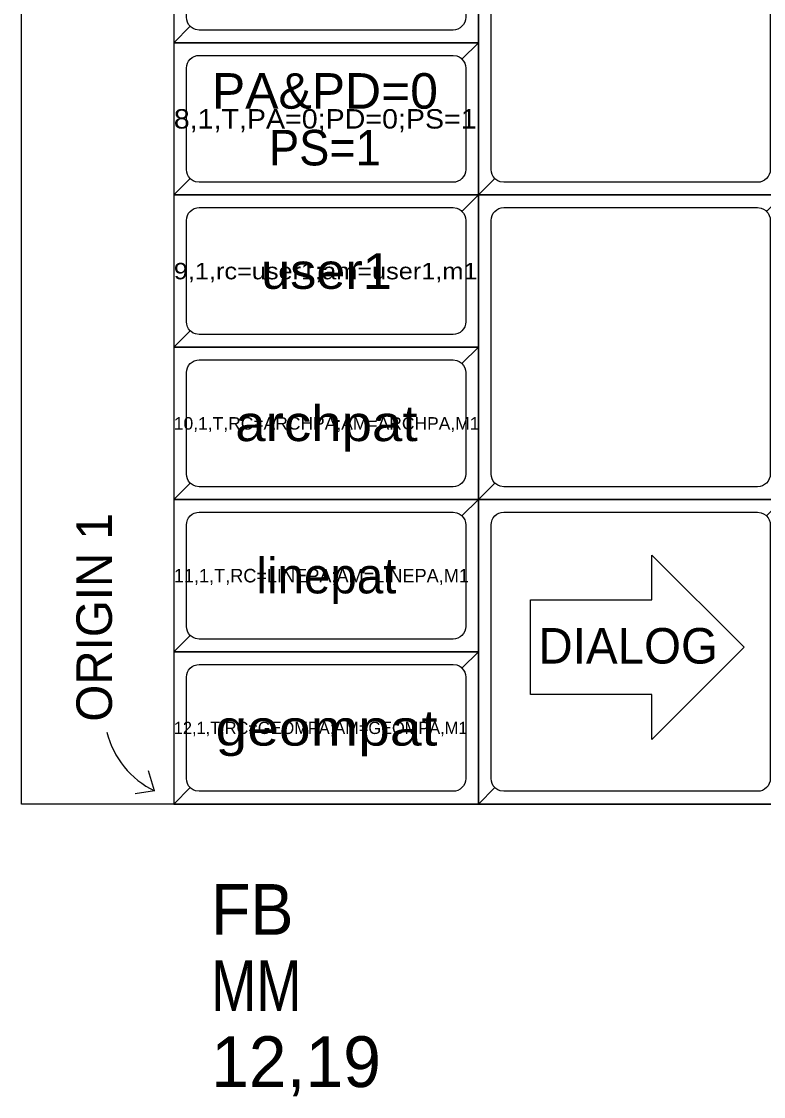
# Model space of a CAD drawing. Extents: x 67896 to 67908, y 49158.5 to 49162.6.
# Drawn here: x 67895.989 to 67897.451, y 49158.457 to 49160.575 of the extents above; entities that cross this region are included whole.
import ezdxf
from ezdxf.enums import TextEntityAlignment as Align

# ---------------------------------------------------------------- set-up
doc = ezdxf.new("R2010")
doc.units = 0
doc.header["$LTSCALE"] = 0.02
for name, color, linetype, lineweight in [('1', 7, 'Continuous', 25), ('2', 7, 'Continuous', 25), ('3', 7, 'Continuous', 25), ('4', 7, 'Continuous', 25), ('5', 7, 'Continuous', 25)]:
    doc.layers.add(name, color=color, linetype=linetype, lineweight=lineweight)
for name, color, linetype in [('63', 7, 'Continuous'), ('7', 7, 'Continuous'), ('8', 7, 'Continuous'), ('9', 7, 'Continuous')]:
    doc.layers.add(name, color=color, linetype=linetype)

msp = doc.modelspace()

# ---------------------------------------------------------------- linework, layer by layer
at = {"layer": '1'}
for points in [[(67896.2889, 49160.5331), (67896.8889, 49160.5331), (67896.8889, 49160.8331), (67896.2889, 49160.8331)], [(67896.8889, 49160.2331), (67897.4889, 49160.2331), (67897.4889, 49160.8331), (67896.8889, 49160.8331)], [(67896.2889, 49160.2331), (67896.8889, 49160.2331), (67896.8889, 49160.5331), (67896.2889, 49160.5331)], [(67896.2889, 49159.9331), (67896.8889, 49159.9331), (67896.8889, 49160.2331), (67896.2889, 49160.2331)], [(67896.8889, 49159.6331), (67897.4889, 49159.6331), (67897.4889, 49160.2331), (67896.8889, 49160.2331)], [(67896.2889, 49159.6331), (67896.8889, 49159.6331), (67896.8889, 49159.9331), (67896.2889, 49159.9331)], [(67896.2889, 49159.3331), (67896.8889, 49159.3331), (67896.8889, 49159.6331), (67896.2889, 49159.6331)], [(67896.8889, 49159.0331), (67897.4889, 49159.0331), (67897.4889, 49159.6331), (67896.8889, 49159.6331)], [(67896.2889, 49159.0331), (67896.8889, 49159.0331), (67896.8889, 49159.3331), (67896.2889, 49159.3331)]]:
    msp.add_lwpolyline(points, close=True, dxfattribs=at)
at = {"layer": '2'}
for points in [[(67907.9889, 49159.0331), (67895.9889, 49159.0331), (67895.9889, 49162.6331), (67907.9889, 49162.6331)], [(67896.2889, 49160.5331), (67896.8889, 49160.5331), (67896.8889, 49160.8331), (67896.2889, 49160.8331)], [(67896.8889, 49160.2331), (67897.4889, 49160.2331), (67897.4889, 49160.8331), (67896.8889, 49160.8331)], [(67896.2889, 49160.2331), (67896.8889, 49160.2331), (67896.8889, 49160.5331), (67896.2889, 49160.5331)], [(67896.2889, 49159.9331), (67896.8889, 49159.9331), (67896.8889, 49160.2331), (67896.2889, 49160.2331)], [(67896.8889, 49159.6331), (67897.4889, 49159.6331), (67897.4889, 49160.2331), (67896.8889, 49160.2331)], [(67896.2889, 49159.6331), (67896.8889, 49159.6331), (67896.8889, 49159.9331), (67896.2889, 49159.9331)], [(67896.2889, 49159.3331), (67896.8889, 49159.3331), (67896.8889, 49159.6331), (67896.2889, 49159.6331)], [(67896.8889, 49159.0331), (67897.4889, 49159.0331), (67897.4889, 49159.6331), (67896.8889, 49159.6331)], [(67896.2889, 49159.0331), (67896.8889, 49159.0331), (67896.8889, 49159.3331), (67896.2889, 49159.3331)]]:
    msp.add_lwpolyline(points, close=True, dxfattribs=at)
at = {"layer": '3'}
for points in [[(67896.8889, 49160.8331), (67896.2889, 49160.8331), (67896.2889, 49160.5331), (67896.3212, 49160.5654), (67896.3181, 49160.5692), (67896.3158, 49160.5735), (67896.3144, 49160.5782), (67896.3139, 49160.5831), (67896.3139, 49160.7831), (67896.3144, 49160.788), (67896.3158, 49160.7927), (67896.3181, 49160.797), (67896.3212, 49160.8008), (67896.3212, 49160.8008), (67896.325, 49160.8039), (67896.3293, 49160.8062), (67896.334, 49160.8076), (67896.3389, 49160.8081), (67896.8389, 49160.8081), (67896.8462, 49160.807), (67896.8507, 49160.8051), (67896.8548, 49160.8024), (67896.8566, 49160.8008)], [(67897.4889, 49160.8331), (67896.8889, 49160.8331), (67896.8889, 49160.2331), (67896.9212, 49160.2654), (67896.9181, 49160.2692), (67896.9158, 49160.2735), (67896.9144, 49160.2782), (67896.9139, 49160.2831), (67896.9139, 49160.7831), (67896.9144, 49160.788), (67896.9158, 49160.7927), (67896.9181, 49160.797), (67896.9212, 49160.8008), (67896.9212, 49160.8008), (67896.925, 49160.8039), (67896.9293, 49160.8062), (67896.934, 49160.8076), (67896.9389, 49160.8081), (67897.4389, 49160.8081), (67897.4462, 49160.807), (67897.4507, 49160.8051), (67897.4548, 49160.8024), (67897.4566, 49160.8008)], [(67896.8889, 49160.5331), (67896.2889, 49160.5331), (67896.2889, 49160.2331), (67896.3212, 49160.2654), (67896.3181, 49160.2692), (67896.3158, 49160.2735), (67896.3144, 49160.2782), (67896.3139, 49160.2831), (67896.3139, 49160.4831), (67896.3144, 49160.488), (67896.3158, 49160.4927), (67896.3181, 49160.497), (67896.3212, 49160.5008), (67896.3212, 49160.5008), (67896.325, 49160.5039), (67896.3293, 49160.5062), (67896.334, 49160.5076), (67896.3389, 49160.5081), (67896.8389, 49160.5081), (67896.8462, 49160.507), (67896.8507, 49160.5051), (67896.8548, 49160.5024), (67896.8566, 49160.5008)], [(67896.8889, 49160.2331), (67896.2889, 49160.2331), (67896.2889, 49159.9331), (67896.3212, 49159.9654), (67896.3181, 49159.9692), (67896.3158, 49159.9735), (67896.3144, 49159.9782), (67896.3139, 49159.9831), (67896.3139, 49160.1831), (67896.3144, 49160.188), (67896.3158, 49160.1927), (67896.3181, 49160.197), (67896.3212, 49160.2008), (67896.3212, 49160.2008), (67896.325, 49160.2039), (67896.3293, 49160.2062), (67896.334, 49160.2076), (67896.3389, 49160.2081), (67896.8389, 49160.2081), (67896.8462, 49160.207), (67896.8507, 49160.2051), (67896.8548, 49160.2024), (67896.8566, 49160.2008)], [(67897.4889, 49160.2331), (67896.8889, 49160.2331), (67896.8889, 49159.6331), (67896.9212, 49159.6654), (67896.9181, 49159.6692), (67896.9158, 49159.6735), (67896.9144, 49159.6782), (67896.9139, 49159.6831), (67896.9139, 49160.1831), (67896.9144, 49160.188), (67896.9158, 49160.1927), (67896.9181, 49160.197), (67896.9212, 49160.2008), (67896.9212, 49160.2008), (67896.925, 49160.2039), (67896.9293, 49160.2062), (67896.934, 49160.2076), (67896.9389, 49160.2081), (67897.4389, 49160.2081), (67897.4462, 49160.207), (67897.4507, 49160.2051), (67897.4548, 49160.2024), (67897.4566, 49160.2008)], [(67896.8889, 49159.9331), (67896.2889, 49159.9331), (67896.2889, 49159.6331), (67896.3212, 49159.6654), (67896.3181, 49159.6692), (67896.3158, 49159.6735), (67896.3144, 49159.6782), (67896.3139, 49159.6831), (67896.3139, 49159.8831), (67896.3144, 49159.888), (67896.3158, 49159.8927), (67896.3181, 49159.897), (67896.3212, 49159.9008), (67896.3212, 49159.9008), (67896.325, 49159.9039), (67896.3293, 49159.9062), (67896.334, 49159.9076), (67896.3389, 49159.9081), (67896.8389, 49159.9081), (67896.8462, 49159.907), (67896.8507, 49159.9051), (67896.8548, 49159.9024), (67896.8566, 49159.9008)], [(67896.8889, 49159.6331), (67896.2889, 49159.6331), (67896.2889, 49159.3331), (67896.3212, 49159.3654), (67896.3181, 49159.3692), (67896.3158, 49159.3735), (67896.3144, 49159.3782), (67896.3139, 49159.3831), (67896.3139, 49159.5831), (67896.3144, 49159.588), (67896.3158, 49159.5927), (67896.3181, 49159.597), (67896.3212, 49159.6008), (67896.3212, 49159.6008), (67896.325, 49159.6039), (67896.3293, 49159.6062), (67896.334, 49159.6076), (67896.3389, 49159.6081), (67896.8389, 49159.6081), (67896.8462, 49159.607), (67896.8507, 49159.6051), (67896.8548, 49159.6024), (67896.8566, 49159.6008)], [(67897.4889, 49159.6331), (67896.8889, 49159.6331), (67896.8889, 49159.0331), (67896.9212, 49159.0654), (67896.9181, 49159.0692), (67896.9158, 49159.0735), (67896.9144, 49159.0782), (67896.9139, 49159.0831), (67896.9139, 49159.5831), (67896.9144, 49159.588), (67896.9158, 49159.5927), (67896.9181, 49159.597), (67896.9212, 49159.6008), (67896.9212, 49159.6008), (67896.925, 49159.6039), (67896.9293, 49159.6062), (67896.934, 49159.6076), (67896.9389, 49159.6081), (67897.4389, 49159.6081), (67897.4462, 49159.607), (67897.4507, 49159.6051), (67897.4548, 49159.6024), (67897.4566, 49159.6008)], [(67896.8889, 49159.3331), (67896.2889, 49159.3331), (67896.2889, 49159.0331), (67896.3212, 49159.0654), (67896.3181, 49159.0692), (67896.3158, 49159.0735), (67896.3144, 49159.0782), (67896.3139, 49159.0831), (67896.3139, 49159.2831), (67896.3144, 49159.288), (67896.3158, 49159.2927), (67896.3181, 49159.297), (67896.3212, 49159.3008), (67896.3212, 49159.3008), (67896.325, 49159.3039), (67896.3293, 49159.3062), (67896.334, 49159.3076), (67896.3389, 49159.3081), (67896.8389, 49159.3081), (67896.8462, 49159.307), (67896.8507, 49159.3051), (67896.8548, 49159.3024), (67896.8566, 49159.3008)]]:
    msp.add_lwpolyline(points, close=True, dxfattribs=at)
at = {"layer": '4'}
for points in [[(67896.2889, 49160.5331), (67896.8889, 49160.5331), (67896.8889, 49160.8331), (67896.8566, 49160.8008), (67896.8597, 49160.797), (67896.862, 49160.7927), (67896.8634, 49160.788), (67896.8639, 49160.7831), (67896.8639, 49160.5831), (67896.8634, 49160.5782), (67896.862, 49160.5735), (67896.8597, 49160.5692), (67896.8566, 49160.5654), (67896.8566, 49160.5654), (67896.8528, 49160.5623), (67896.8485, 49160.56), (67896.8438, 49160.5586), (67896.8389, 49160.5581), (67896.3389, 49160.5581), (67896.3316, 49160.5592), (67896.3271, 49160.5611), (67896.323, 49160.5638), (67896.3212, 49160.5654)], [(67896.8889, 49160.2331), (67897.4889, 49160.2331), (67897.4889, 49160.8331), (67897.4566, 49160.8008), (67897.4597, 49160.797), (67897.462, 49160.7927), (67897.4634, 49160.788), (67897.4639, 49160.7831), (67897.4639, 49160.2831), (67897.4634, 49160.2782), (67897.462, 49160.2735), (67897.4597, 49160.2692), (67897.4566, 49160.2654), (67897.4566, 49160.2654), (67897.4528, 49160.2623), (67897.4485, 49160.26), (67897.4438, 49160.2586), (67897.4389, 49160.2581), (67896.9389, 49160.2581), (67896.9316, 49160.2592), (67896.9271, 49160.2611), (67896.923, 49160.2638), (67896.9212, 49160.2654)], [(67896.2889, 49160.2331), (67896.8889, 49160.2331), (67896.8889, 49160.5331), (67896.8566, 49160.5008), (67896.8597, 49160.497), (67896.862, 49160.4927), (67896.8634, 49160.488), (67896.8639, 49160.4831), (67896.8639, 49160.2831), (67896.8634, 49160.2782), (67896.862, 49160.2735), (67896.8597, 49160.2692), (67896.8566, 49160.2654), (67896.8566, 49160.2654), (67896.8528, 49160.2623), (67896.8485, 49160.26), (67896.8438, 49160.2586), (67896.8389, 49160.2581), (67896.3389, 49160.2581), (67896.3316, 49160.2592), (67896.3271, 49160.2611), (67896.323, 49160.2638), (67896.3212, 49160.2654)], [(67896.2889, 49159.9331), (67896.8889, 49159.9331), (67896.8889, 49160.2331), (67896.8566, 49160.2008), (67896.8597, 49160.197), (67896.862, 49160.1927), (67896.8634, 49160.188), (67896.8639, 49160.1831), (67896.8639, 49159.9831), (67896.8634, 49159.9782), (67896.862, 49159.9735), (67896.8597, 49159.9692), (67896.8566, 49159.9654), (67896.8566, 49159.9654), (67896.8528, 49159.9623), (67896.8485, 49159.96), (67896.8438, 49159.9586), (67896.8389, 49159.9581), (67896.3389, 49159.9581), (67896.3316, 49159.9592), (67896.3271, 49159.9611), (67896.323, 49159.9638), (67896.3212, 49159.9654)], [(67896.8889, 49159.6331), (67897.4889, 49159.6331), (67897.4889, 49160.2331), (67897.4566, 49160.2008), (67897.4597, 49160.197), (67897.462, 49160.1927), (67897.4634, 49160.188), (67897.4639, 49160.1831), (67897.4639, 49159.6831), (67897.4634, 49159.6782), (67897.462, 49159.6735), (67897.4597, 49159.6692), (67897.4566, 49159.6654), (67897.4566, 49159.6654), (67897.4528, 49159.6623), (67897.4485, 49159.66), (67897.4438, 49159.6586), (67897.4389, 49159.6581), (67896.9389, 49159.6581), (67896.9316, 49159.6592), (67896.9271, 49159.6611), (67896.923, 49159.6638), (67896.9212, 49159.6654)], [(67896.2889, 49159.6331), (67896.8889, 49159.6331), (67896.8889, 49159.9331), (67896.8566, 49159.9008), (67896.8597, 49159.897), (67896.862, 49159.8927), (67896.8634, 49159.888), (67896.8639, 49159.8831), (67896.8639, 49159.6831), (67896.8634, 49159.6782), (67896.862, 49159.6735), (67896.8597, 49159.6692), (67896.8566, 49159.6654), (67896.8566, 49159.6654), (67896.8528, 49159.6623), (67896.8485, 49159.66), (67896.8438, 49159.6586), (67896.8389, 49159.6581), (67896.3389, 49159.6581), (67896.3316, 49159.6592), (67896.3271, 49159.6611), (67896.323, 49159.6638), (67896.3212, 49159.6654)], [(67896.2889, 49159.3331), (67896.8889, 49159.3331), (67896.8889, 49159.6331), (67896.8566, 49159.6008), (67896.8597, 49159.597), (67896.862, 49159.5927), (67896.8634, 49159.588), (67896.8639, 49159.5831), (67896.8639, 49159.3831), (67896.8634, 49159.3782), (67896.862, 49159.3735), (67896.8597, 49159.3692), (67896.8566, 49159.3654), (67896.8566, 49159.3654), (67896.8528, 49159.3623), (67896.8485, 49159.36), (67896.8438, 49159.3586), (67896.8389, 49159.3581), (67896.3389, 49159.3581), (67896.3316, 49159.3592), (67896.3271, 49159.3611), (67896.323, 49159.3638), (67896.3212, 49159.3654)], [(67896.8889, 49159.0331), (67897.4889, 49159.0331), (67897.4889, 49159.6331), (67897.4566, 49159.6008), (67897.4597, 49159.597), (67897.462, 49159.5927), (67897.4634, 49159.588), (67897.4639, 49159.5831), (67897.4639, 49159.0831), (67897.4634, 49159.0782), (67897.462, 49159.0735), (67897.4597, 49159.0692), (67897.4566, 49159.0654), (67897.4566, 49159.0654), (67897.4528, 49159.0623), (67897.4485, 49159.06), (67897.4438, 49159.0586), (67897.4389, 49159.0581), (67896.9389, 49159.0581), (67896.9316, 49159.0592), (67896.9271, 49159.0611), (67896.923, 49159.0638), (67896.9212, 49159.0654)], [(67896.2889, 49159.0331), (67896.8889, 49159.0331), (67896.8889, 49159.3331), (67896.8566, 49159.3008), (67896.8597, 49159.297), (67896.862, 49159.2927), (67896.8634, 49159.288), (67896.8639, 49159.2831), (67896.8639, 49159.0831), (67896.8634, 49159.0782), (67896.862, 49159.0735), (67896.8597, 49159.0692), (67896.8566, 49159.0654), (67896.8566, 49159.0654), (67896.8528, 49159.0623), (67896.8485, 49159.06), (67896.8438, 49159.0586), (67896.8389, 49159.0581), (67896.3389, 49159.0581), (67896.3316, 49159.0592), (67896.3271, 49159.0611), (67896.323, 49159.0638), (67896.3212, 49159.0654)]]:
    msp.add_lwpolyline(points, close=True, dxfattribs=at)
at = {"layer": '5'}
for q in [(67896.239, 49159.0982), (67896.2129, 49159.0532)]:
    msp.add_line((67896.2509, 49159.0591), q, dxfattribs=at)
msp.add_lwpolyline([(67897.2305, 49159.5236), (67897.4121, 49159.3421), (67897.2305, 49159.1605), (67897.2305, 49159.2486), (67896.9918, 49159.2486), (67896.9918, 49159.4356), (67897.2305, 49159.4356)], close=True, dxfattribs=at)
msp.add_arc((67896.3275, 49159.217), 0.1755, 193.9079, 244.0981, dxfattribs=at)

# ---------------------------------------------------------------- texts
for s, width, p in [('PA&PD=0', 1.05, (67896.5866, 49160.4031)), ('PS=1', 0.95, (67896.5866, 49160.2913))]:
    msp.add_text(s, height=0.07, dxfattribs=dict(at, width=width)).set_placement(p, align=Align.CENTER)
msp.add_text('ORIGIN 1', height=0.07, rotation=90, dxfattribs=at).set_placement((67896.1671, 49159.4008), align=Align.CENTER)
msp.add_text('DIALOG', height=0.07, dxfattribs=at).set_placement((67897.184, 49159.3098), align=Align.CENTER)
at = {"layer": '63'}
for s, height, width, p in [('8,1,T,PA=0;PD=0;PS=1', 0.0383, 1.1, (67896.2889, 49160.3639)), ('9,1,rc=user1;am=user1,m1', 0.0324, 1.15, (67896.2889, 49160.0669)), ('10,1,T,RC=ARCHPA;AM=ARCHPA,M1', 0.0245, 1.05, (67896.2889, 49159.7708)), ('FB', 0.1, 0.95, (67896.3623, 49158.7754)), ('MM', 0.1, 0.8, (67896.3623, 49158.6254))]:
    msp.add_text(s, height=height, dxfattribs=dict(at, width=width)).set_placement(p)
for s, height, p in [('11,1,T,RC=LINEPA;AM=LINEPA,M1', 0.0267, (67896.2889, 49159.4697)), ('12,1,T,RC=GEOMPA;AM=GEOMPA,M1', 0.0241, (67896.2889, 49159.171)), ('12,19', 0.1, (67896.3623, 49158.4754))]:
    msp.add_text(s, height=height, dxfattribs=at).set_placement(p)
at = {"layer": '7'}
for s, width, p in [('user1', 1.1, (67896.5896, 49160.0481)), ('archpat', 1.15, (67896.5896, 49159.7481))]:
    msp.add_text(s, height=0.07, dxfattribs=dict(at, width=width)).set_placement(p, align=Align.CENTER)
at = {"layer": '8'}
msp.add_text('linepat', height=0.07, dxfattribs=at).set_placement((67896.5896, 49159.4481), align=Align.CENTER)
at = {"layer": '9', "width": 1.2}
msp.add_text('geompat', height=0.07, dxfattribs=at).set_placement((67896.5897, 49159.1481), align=Align.CENTER)

doc.saveas('drawing.dxf')
